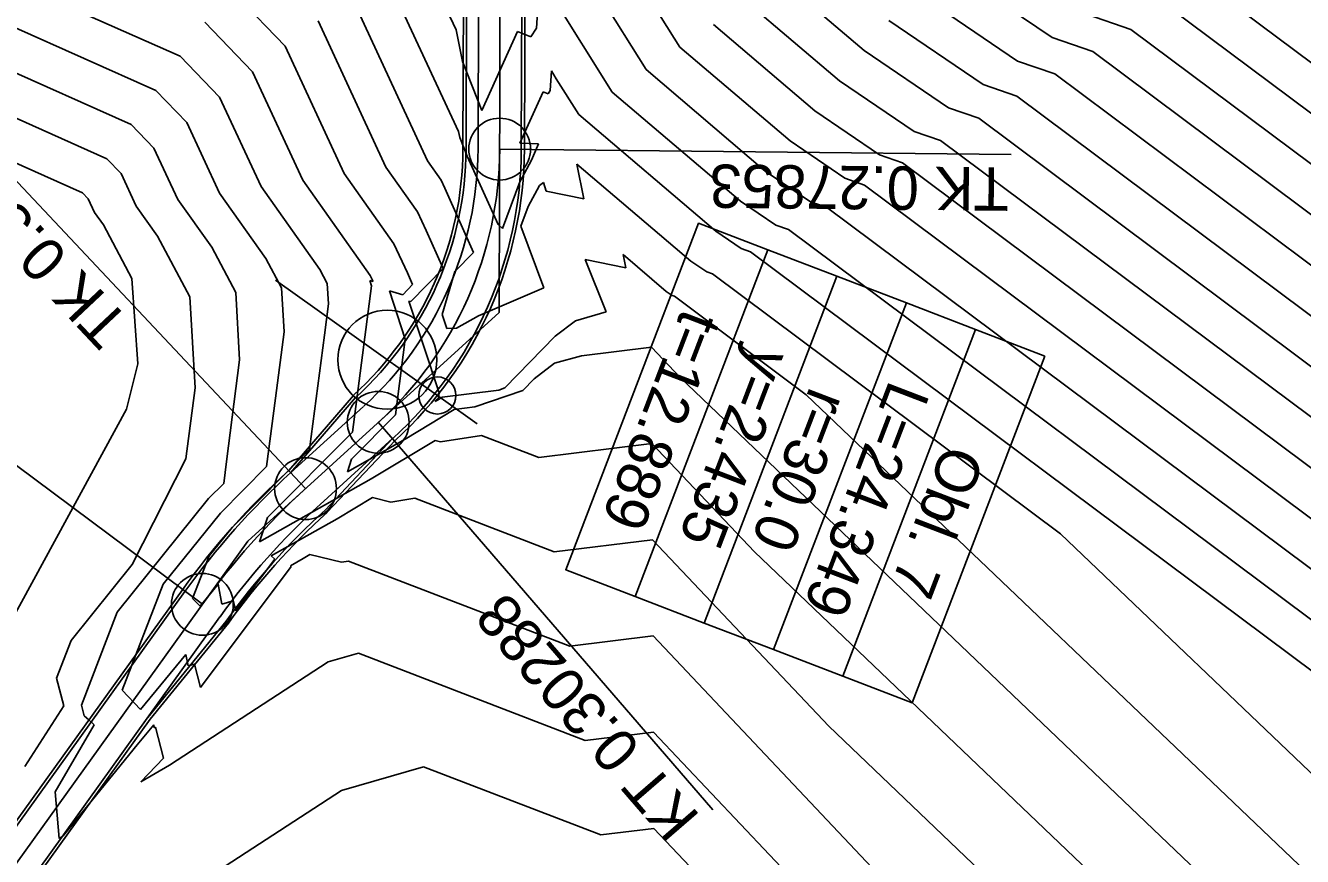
# Model space of a CAD drawing. Extents: x -549394 to -546608, y -1037055 to -1033629.
# Drawn here: x -546964.3 to -546861.1, y -1036015.8 to -1035948.7 of the extents above; entities that cross this region are included whole.
import ezdxf

# ---------------------------------------------------------------- set-up
doc = ezdxf.new("R2010")
doc.units = 0
for name, color, linetype in [('hlavni_vrst', 7, 'Continuous'), ('norm_vrst', 7, 'Continuous'), ('POLYGONY_SITUACE_PO', 7, 'Continuous'), ('u_sirka_7m', 7, 'Continuous'), ('x_navrh_C31', 7, 'Continuous'), ('x_osa_C31', 7, 'Continuous'), ('x_popis_oblouky_C31', 7, 'Continuous'), ('x_popis_pricne_rezy_C31', 7, 'Continuous')]:
    doc.layers.add(name, color=color, linetype=linetype)

msp = doc.modelspace()

# ---------------------------------------------------------------- linework, layer by layer
at = {"layer": 'hlavni_vrst'}
for p, q in [((-546929.53, -1035949), (-546932.73, -1035942.1)), ((-546922.77, -1035944.62), (-546923.02, -1035948.86)), ((-546896.52, -1035950.68), (-546903.28, -1035944.93)), ((-546916.89, -1035954.03), (-546921.74, -1035946.29)), ((-546853.89, -1035960.59), (-546871.88, -1035947.16)), ((-546946, -1035952.39), (-546949.85, -1035948.39)), ((-546929.01, -1035951.57), (-546929.53, -1035949)), ((-546924.57, -1035949.13), (-546927.44, -1035955.51)), ((-546923.47, -1035949.56), (-546924.57, -1035949.13)), ((-546923.02, -1035948.86), (-546923.47, -1035949.56)), ((-546889.7, -1035955.31), (-546896.52, -1035950.68)), ((-546927.44, -1035955.51), (-546929.01, -1035951.57)), ((-546941.93, -1035961.15), (-546946, -1035952.39)), ((-546906.53, -1035962.84), (-546916.89, -1035954.03)), ((-546959.74, -1035962.17), (-546975.08, -1035955.33)), ((-546887.26, -1035956.15), (-546889.7, -1035955.31)), ((-546840.8, -1035990.83), (-546887.26, -1035956.15)), ((-546936.46, -1035968.86), (-546941.93, -1035961.15)), ((-546959.27, -1035962.67), (-546959.74, -1035962.17)), ((-546958.76, -1035963.76), (-546959.27, -1035962.67)), ((-546903.67, -1035964.78), (-546906.53, -1035962.84)), ((-546958.04, -1035964.77), (-546958.76, -1035963.76)), ((-546955.74, -1035969.11), (-546958.04, -1035964.77)), ((-546902.64, -1035965.13), (-546903.67, -1035964.78)), ((-546839.53, -1036012.25), (-546902.64, -1035965.13)), ((-546955.26, -1035976), (-546955.74, -1035969.11)), ((-546937.9, -1035981.51), (-546936.36, -1035969.69)), ((-546936.5, -1035969.27), (-546936.24, -1035969.34)), ((-546936.36, -1035969.69), (-546936.5, -1035969.27)), ((-546936.24, -1035969.34), (-546936.46, -1035968.86)), ((-546956.18, -1035979.65), (-546955.26, -1035976)), ((-546965.68, -1035997.09), (-546956.18, -1035979.65)), ((-546944.77, -1035988.42), (-546937.9, -1035981.51)), ((-546931.23, -1035982.19), (-546936.4, -1035985.3)), ((-546930.79, -1035982.3), (-546931.23, -1035982.19)), ((-546927.47, -1035981.78), (-546930.79, -1035982.3)), ((-546922.83, -1035983.57), (-546927.47, -1035981.78)), ((-546913.69, -1035982.43), (-546922.83, -1035983.57)), ((-546905.4, -1035991.19), (-546913.69, -1035982.43)), ((-546936.4, -1035985.3), (-546945.41, -1035990.38)), ((-546945.41, -1035990.38), (-546944.77, -1035988.42)), ((-546859.63, -1036034.83), (-546905.4, -1035991.19))]:
    msp.add_line(p, q, dxfattribs=at)
at = {"layer": 'norm_vrst'}
for p, q in [((-546911.44, -1035950.39), (-546919.87, -1035936.95)), ((-546914.16, -1035952.21), (-546922.05, -1035939.64)), ((-546881.32, -1035949.63), (-546890.52, -1035943.38)), ((-546929.33, -1035957.21), (-546935.39, -1035944.16)), ((-546943.35, -1035950.33), (-546947.87, -1035945.63)), ((-546884.11, -1035951.53), (-546892.52, -1035945.81)), ((-546856.51, -1035954.54), (-546868.8, -1035945.36)), ((-546951.83, -1035951.14), (-546962.16, -1035946.54)), ((-546931.84, -1035959.58), (-546938.04, -1035946.22)), ((-546898.52, -1035953.11), (-546906, -1035946.75)), ((-546874.96, -1035948.96), (-546878.53, -1035947.74)), ((-546953.81, -1035953.9), (-546965.39, -1035948.74)), ((-546935.2, -1035960.1), (-546940.69, -1035948.27)), ((-546900.52, -1035955.54), (-546908.72, -1035948.57)), ((-546886.91, -1035953.42), (-546894.52, -1035948.24)), ((-546851.27, -1035966.64), (-546874.96, -1035948.96)), ((-546878.03, -1035950.75), (-546881.32, -1035949.63)), ((-546955.79, -1035956.66), (-546968.62, -1035950.94)), ((-546948.65, -1035954.44), (-546951.83, -1035951.14)), ((-546938.57, -1035960.62), (-546943.35, -1035950.33)), ((-546902.52, -1035957.97), (-546911.44, -1035950.39)), ((-546848.65, -1035972.69), (-546878.03, -1035950.75)), ((-546904.52, -1035960.41), (-546914.16, -1035952.21)), ((-546881.11, -1035952.55), (-546884.11, -1035951.53)), ((-546957.77, -1035959.42), (-546971.85, -1035953.14)), ((-546921.81, -1035952.32), (-546921.91, -1035953.91)), ((-546921.43, -1035952.95), (-546921.81, -1035952.32)), ((-546919.61, -1035955.85), (-546921.43, -1035952.95)), ((-546892.49, -1035957.21), (-546898.52, -1035953.11)), ((-546846.04, -1035978.74), (-546881.11, -1035952.55)), ((-546951.31, -1035956.5), (-546953.81, -1035953.9)), ((-546922.49, -1035954.01), (-546924.36, -1035958.17)), ((-546922.08, -1035954.17), (-546922.49, -1035954.01)), ((-546921.91, -1035953.91), (-546922.08, -1035954.17)), ((-546884.19, -1035954.35), (-546886.91, -1035953.42)), ((-546945.3, -1035961.67), (-546948.65, -1035954.44)), ((-546843.42, -1035984.79), (-546884.19, -1035954.35)), ((-546908.53, -1035965.27), (-546919.61, -1035955.85)), ((-546895.29, -1035959.1), (-546900.52, -1035955.54)), ((-546953.96, -1035958.56), (-546955.79, -1035956.66)), ((-546948.66, -1035962.19), (-546951.31, -1035956.5)), ((-546929.23, -1035957.71), (-546929.33, -1035957.21)), ((-546890.34, -1035957.94), (-546892.49, -1035957.21)), ((-546928.63, -1035959.21), (-546929.23, -1035957.71)), ((-546924.36, -1035958.17), (-546922.86, -1035958.22)), ((-546922.86, -1035958.22), (-546923.43, -1035959.54)), ((-546898.08, -1035961), (-546902.52, -1035957.97)), ((-546838.18, -1035996.88), (-546890.34, -1035957.94)), ((-546956.61, -1035960.61), (-546957.77, -1035959.42)), ((-546952.03, -1035962.71), (-546953.96, -1035958.56)), ((-546926.13, -1035964.73), (-546928.63, -1035959.21)), ((-546893.42, -1035959.74), (-546895.29, -1035959.1)), ((-546932.64, -1035963.71), (-546935.2, -1035960.1)), ((-546930.73, -1035961.14), (-546931.84, -1035959.58)), ((-546923.43, -1035959.54), (-546924.36, -1035961.28)), ((-546919.75, -1035959.86), (-546919.2, -1035962.66)), ((-546910.53, -1035967.7), (-546919.75, -1035959.86)), ((-546900.87, -1035962.89), (-546904.52, -1035960.41)), ((-546835.57, -1036002.93), (-546893.42, -1035959.74)), ((-546955.4, -1035963.24), (-546956.61, -1035960.61)), ((-546934.55, -1035966.29), (-546938.57, -1035960.62)), ((-546930.43, -1035961.79), (-546930.73, -1035961.14)), ((-546924.36, -1035961.28), (-546925.78, -1035965.06)), ((-546922.45, -1035961.34), (-546922.78, -1035961.59)), ((-546922.25, -1035962.05), (-546922.45, -1035961.34)), ((-546896.49, -1035961.54), (-546898.08, -1035961)), ((-546832.95, -1036008.98), (-546896.49, -1035961.54)), ((-546944.92, -1035967.47), (-546948.66, -1035962.19)), ((-546940.54, -1035968.38), (-546945.3, -1035961.67)), ((-546928.11, -1035966.99), (-546930.43, -1035961.79)), ((-546922.78, -1035961.59), (-546923.7, -1035963.29)), ((-546919.2, -1035962.66), (-546922.25, -1035962.05)), ((-546953.67, -1035965.67), (-546955.4, -1035963.24)), ((-546949.29, -1035966.57), (-546952.03, -1035962.71)), ((-546923.7, -1035963.29), (-546924.29, -1035964.87)), ((-546899.57, -1035963.33), (-546900.87, -1035962.89)), ((-546830.33, -1036015.03), (-546899.57, -1035963.33)), ((-546931.94, -1035965.22), (-546932.64, -1035963.71)), ((-546951.05, -1035970.59), (-546953.67, -1035965.67)), ((-546930.57, -1035968.29), (-546931.94, -1035965.22)), ((-546925.78, -1035965.06), (-546926.13, -1035964.73)), ((-546924.29, -1035964.87), (-546922.42, -1035969.85)), ((-546906.46, -1035966.68), (-546908.53, -1035965.27)), ((-546947.35, -1035970.22), (-546949.29, -1035966.57)), ((-546933.45, -1035968.65), (-546934.55, -1035966.29)), ((-546905.72, -1035966.93), (-546906.46, -1035966.68)), ((-546943.65, -1035969.86), (-546944.92, -1035967.47)), ((-546929.62, -1035968.54), (-546928.11, -1035966.99)), ((-546915.81, -1035968.23), (-546919.08, -1035967.57)), ((-546919.08, -1035967.57), (-546917.39, -1035971.78)), ((-546916.02, -1035967.16), (-546915.81, -1035968.23)), ((-546912.53, -1035970.14), (-546916.02, -1035967.16)), ((-546909.25, -1035968.57), (-546910.53, -1035967.7)), ((-546860.09, -1036001), (-546905.72, -1035966.93)), ((-546939.95, -1035969.49), (-546940.54, -1035968.38)), ((-546933.04, -1035969.59), (-546933.45, -1035968.65)), ((-546933.19, -1035970.96), (-546930.57, -1035968.29)), ((-546930.65, -1035972.01), (-546929.62, -1035968.54)), ((-546908.8, -1035968.73), (-546909.25, -1035968.57)), ((-546880.65, -1035989.74), (-546908.8, -1035968.73)), ((-546939.85, -1035971.15), (-546939.95, -1035969.49)), ((-546933.84, -1035970.41), (-546933.04, -1035969.59)), ((-546950.63, -1035977.92), (-546951.05, -1035970.59)), ((-546947.04, -1035975.67), (-546947.35, -1035970.22)), ((-546943.44, -1035973.41), (-546943.65, -1035969.86)), ((-546934.92, -1035970.09), (-546933.84, -1035970.41)), ((-546933.63, -1035974.01), (-546934.92, -1035970.09)), ((-546922.42, -1035969.85), (-546927.71, -1035972.12)), ((-546912.05, -1035970.46), (-546912.53, -1035970.14)), ((-546911.87, -1035970.52), (-546912.05, -1035970.46)), ((-546901.21, -1035978.49), (-546911.87, -1035970.52)), ((-546940.17, -1035973.67), (-546939.85, -1035971.15)), ((-546933.35, -1035970.92), (-546933.19, -1035970.96)), ((-546930.9, -1035978.33), (-546933.35, -1035970.92)), ((-546917.39, -1035971.78), (-546919.88, -1035972.51)), ((-546930.26, -1035973.14), (-546930.65, -1035972.01)), ((-546927.71, -1035972.12), (-546929.48, -1035973.1)), ((-546919.88, -1035972.51), (-546921.52, -1035973.77)), ((-546944.13, -1035978.78), (-546943.44, -1035973.41)), ((-546941.37, -1035982.89), (-546940.17, -1035973.67)), ((-546929.48, -1035973.1), (-546930.26, -1035973.14)), ((-546921.52, -1035973.77), (-546925.57, -1035977.94)), ((-546934.43, -1035980.12), (-546933.63, -1035974.01)), ((-546913.73, -1035974.65), (-546919.38, -1035975.36)), ((-546911.41, -1035977.11), (-546913.73, -1035974.65)), ((-546948.09, -1035983.89), (-546947.04, -1035975.67)), ((-546921.57, -1035975.95), (-546923.2, -1035977.2)), ((-546919.38, -1035975.36), (-546921.57, -1035975.95)), ((-546951.37, -1035983.68), (-546950.63, -1035977.92)), ((-546925.57, -1035977.94), (-546926.08, -1035978.11)), ((-546923.2, -1035977.2), (-546924.14, -1035978.16)), ((-546854.08, -1036031.78), (-546911.41, -1035977.11)), ((-546944.85, -1035984.28), (-546944.13, -1035978.78)), ((-546930.9, -1035978.86), (-546931.21, -1035979.03)), ((-546931.21, -1035979.03), (-546931.19, -1035978.96)), ((-546931.19, -1035978.96), (-546930.95, -1035978.73)), ((-546930.95, -1035978.73), (-546930.9, -1035978.33)), ((-546930.64, -1035978.7), (-546930.9, -1035978.86)), ((-546926.08, -1035978.11), (-546930.64, -1035978.7)), ((-546924.14, -1035978.16), (-546928, -1035979.47)), ((-546848.53, -1036028.72), (-546901.21, -1035978.49)), ((-546937.98, -1035983.69), (-546934.43, -1035980.12)), ((-546929.67, -1035979.69), (-546933.65, -1035982.08)), ((-546928, -1035979.47), (-546929.67, -1035979.69)), ((-546933.65, -1035982.08), (-546938.31, -1035984.71)), ((-546947.64, -1035989.21), (-546941.37, -1035982.89)), ((-546955.71, -1035992.22), (-546951.37, -1035983.68)), ((-546948.59, -1035988.05), (-546944.85, -1035984.28)), ((-546948.32, -1035985.67), (-546948.09, -1035983.89)), ((-546938.31, -1035984.71), (-546937.98, -1035983.69)), ((-546949.54, -1035986.89), (-546948.32, -1035985.67)), ((-546956.94, -1035996.07), (-546949.54, -1035986.89)), ((-546936.28, -1035986.8), (-546939.14, -1035988.52)), ((-546934.79, -1035987.17), (-546936.28, -1035986.8)), ((-546932.85, -1035986.86), (-546934.79, -1035987.17)), ((-546921.58, -1035991.19), (-546932.85, -1035986.86)), ((-546953.22, -1035993.79), (-546948.59, -1035988.05)), ((-546949.5, -1035991.51), (-546947.64, -1035989.21)), ((-546939.14, -1035988.52), (-546944.47, -1035991.52)), ((-546913.65, -1035990.21), (-546921.58, -1035991.19)), ((-546899.39, -1036005.27), (-546913.65, -1035990.21)), ((-546842.98, -1036025.66), (-546880.65, -1035989.74)), ((-546950.83, -1035994.96), (-546949.5, -1035991.51)), ((-546941.34, -1035991.4), (-546941.89, -1035991.74)), ((-546938.8, -1035992.03), (-546941.34, -1035991.4)), ((-546960.66, -1035998.36), (-546955.71, -1035992.22)), ((-546942.87, -1035992.37), (-546950.2, -1036002.14)), ((-546944.19, -1035991.77), (-546947.33, -1035995.96)), ((-546944.47, -1035991.52), (-546944.19, -1035991.77)), ((-546941.89, -1035991.74), (-546942.92, -1035992.32)), ((-546942.92, -1035992.32), (-546942.87, -1035992.37)), ((-546938.22, -1035991.94), (-546938.8, -1035992.03)), ((-546920.33, -1035998.82), (-546938.22, -1035991.94)), ((-546956.53, -1036002.38), (-546953.22, -1035993.79)), ((-546948.76, -1035993.79), (-546950.23, -1035995.58)), ((-546948.46, -1035995.42), (-546948.76, -1035993.79)), ((-546950.23, -1035995.58), (-546950.83, -1035994.96)), ((-546947.54, -1035995.16), (-546948.46, -1035995.42)), ((-546947.33, -1035995.96), (-546947.54, -1035995.16)), ((-546959.83, -1036003.57), (-546956.94, -1035996.07)), ((-546961.83, -1036001.39), (-546960.66, -1035998.36)), ((-546913.6, -1035997.98), (-546920.33, -1035998.82)), ((-546893.38, -1036019.35), (-546913.6, -1035997.98)), ((-546951.37, -1035999.49), (-546955.04, -1036003.94)), ((-546951.2, -1036000.41), (-546951.37, -1035999.49)), ((-546937.43, -1035999.39), (-546939.86, -1036000.09)), ((-546919.08, -1036006.45), (-546937.43, -1035999.39)), ((-546939.86, -1036000.09), (-546952.71, -1036008.42)), ((-546950.68, -1036000.26), (-546951.2, -1036000.41)), ((-546950.2, -1036002.14), (-546950.68, -1036000.26)), ((-546961.24, -1036003.64), (-546961.83, -1036001.39)), ((-546955.04, -1036003.94), (-546956.53, -1036002.38)), ((-546964.39, -1036008.54), (-546961.24, -1036003.64)), ((-546961.24, -1036003.64), (-546961.24, -1036003.64)), ((-546961.24, -1036003.64), (-546961.24, -1036003.64)), ((-546959.6, -1036004.45), (-546959.83, -1036003.57)), ((-546959.22, -1036004.76), (-546959.6, -1036004.45)), ((-546958.8, -1036005.16), (-546959.22, -1036004.76)), ((-546961.96, -1036010.58), (-546958.8, -1036005.16)), ((-546953.98, -1036005.18), (-546955.32, -1036006.8)), ((-546953.94, -1036005.4), (-546953.98, -1036005.18)), ((-546953.82, -1036005.37), (-546953.94, -1036005.4)), ((-546953.19, -1036007.87), (-546953.82, -1036005.37)), ((-546913.56, -1036005.76), (-546919.08, -1036006.45)), ((-546887.38, -1036033.42), (-546913.56, -1036005.76)), ((-546865.18, -1036037.89), (-546899.39, -1036005.27)), ((-546955.32, -1036006.8), (-546961.29, -1036014.15)), ((-546955.01, -1036009.77), (-546953.19, -1036007.87)), ((-546952.71, -1036008.42), (-546955.01, -1036009.77)), ((-546932.16, -1036008.56), (-546938.78, -1036010.48)), ((-546917.83, -1036014.07), (-546932.16, -1036008.56)), ((-546961.63, -1036014.36), (-546961.96, -1036010.58)), ((-546938.78, -1036010.48), (-546948.21, -1036016.59)), ((-546961.29, -1036014.15), (-546961.63, -1036014.36)), ((-546913.52, -1036013.54), (-546917.83, -1036014.07)), ((-546881.96, -1036046.88), (-546913.52, -1036013.54))]:
    msp.add_line(p, q, dxfattribs=at)
at = {"layer": 'POLYGONY_SITUACE_PO'}
for centre in [(-546926, -1035958.64), (-546935.82, -1035980.72), (-546941.7, -1035986.08), (-546950.04, -1035995.43)]:
    msp.add_circle(centre, 2.5, dxfattribs=at)
at = {"layer": 'u_sirka_7m'}
for centre, radius in [((-546935.09, -1035975.66), 4), ((-546931.04, -1035978.55), 1.5)]:
    msp.add_circle(centre, radius, dxfattribs=at)
at = {"layer": 'x_navrh_C31'}
for p, q in [((-546928.97, -1035958.63), (-546928.92, -1035943.59)), ((-546928.72, -1035958.63), (-546928.67, -1035943.6)), ((-546927.75, -1035958.63), (-546927.7, -1035943.6)), ((-546924.25, -1035958.64), (-546924.2, -1035943.61)), ((-546937.83, -1035978.54), (-546943.06, -1035984.61)), ((-546937.65, -1035978.71), (-546942.88, -1035984.78)), ((-546942.88, -1035984.78), (-546937, -1035979.43)), ((-546940.53, -1035987.37), (-546934.63, -1035982.01)), ((-546940.12, -1035987.82), (-546934.63, -1035982.01)), ((-546939.94, -1035987.99), (-546934.45, -1035982.18)), ((-547002.86, -1036065.86), (-546951.46, -1035994.4)), ((-547000.02, -1036067.9), (-546948.62, -1035996.45)), ((-546948.13, -1035996.8), (-546954.46, -1036004.57)), ((-546947.93, -1035996.95), (-546954.26, -1036004.72))]:
    msp.add_line(p, q, dxfattribs=at)
for points in [[(-546924, -1035958.64), (-546923.95, -1035943.61)], [(-546997.24, -1036057.61), (-546951.66, -1035994.26)], [(-546999.81, -1036068.05), (-546954.26, -1036004.72)]]:
    msp.add_lwpolyline(points, dxfattribs=at)
for centre, radius, start, end in [((-546956, -1035958.53), 27.03, 312.2581, 359.7992), ((-546956, -1035958.53), 27.28, 312.2902, 359.7992), ((-546956, -1035958.53), 28.25, 312.2902, 359.7992), ((-546956, -1035958.53), 31.75, 312.2902, 359.7992), ((-546956, -1035958.53), 32, 312.3431, 359.7992), ((-546901.33, -1036030.46), 62, 132.3042, 144.2713), ((-546901.33, -1036030.46), 61.75, 132.2902, 144.2713), ((-546901.33, -1036030.46), 58.25, 132.2902, 144.2713), ((-546901.33, -1036030.46), 57.65, 132.2902, 144.2713), ((-546901.33, -1036030.46), 57.4, 132.2902, 144.2788)]:
    msp.add_arc(centre, radius, start, end, dxfattribs=at)
at = {"layer": 'x_osa_C31'}
msp.add_lwpolyline([(-547007, -1036074.62), (-546946.36, -1035990.32), (-546926.05, -1035971.84), (-546925.92, -1035933.3), (-546935.95, -1035920.32)], dxfattribs=at)
for centre, radius, start, end in [((-546956, -1035958.53), 30, 312.2902, 359.7992), ((-546901.33, -1036030.46), 60, 132.2902, 144.2713)]:
    msp.add_arc(centre, radius, start, end, dxfattribs=at)
at = {"layer": 'x_popis_oblouky_C31'}
for points in [[(-546941.7, -1035986.08), (-546970.07, -1035955.96)], [(-546884.63, -1035959.07), (-546926, -1035958.64)], [(-546950.04, -1035995.43), (-546983.22, -1035970.71)], [(-546908.77, -1036012.03), (-546935.82, -1035980.72)]]:
    msp.add_lwpolyline(points, dxfattribs=at)
for points in [[(-546904.32, -1035966.78), (-546915.05, -1035994.79), (-546920.66, -1035992.64), (-546909.92, -1035964.63)], [(-546898.72, -1035968.92), (-546909.45, -1035996.94), (-546915.05, -1035994.79), (-546904.32, -1035966.78)], [(-546893.11, -1035971.07), (-546903.85, -1035999.08), (-546909.45, -1035996.94), (-546898.72, -1035968.92)], [(-546887.51, -1035973.22), (-546898.25, -1036001.23), (-546903.85, -1035999.08), (-546893.11, -1035971.07)], [(-546881.91, -1035975.37), (-546892.64, -1036003.38), (-546898.25, -1036001.23), (-546887.51, -1035973.22)]]:
    msp.add_lwpolyline(points, close=True, dxfattribs=at)
at = {"layer": 'x_popis_pricne_rezy_C31'}
msp.add_lwpolyline([(-546927.83, -1035980.84), (-546935.98, -1035975.03), (-546944.12, -1035969.22)], dxfattribs=at)

# ---------------------------------------------------------------- texts
at = {"layer": 'x_popis_oblouky_C31'}
for s, rotation, p in [('TK 0.31217', 133.2795, (-546955.77, -1035972.6)), ('TK 0.27853', 179.395, (-546884.8, -1035960.13)), ('t=12.889', 249.0513, (-546911.22, -1035971.4)), ('y=2.435', 249.0513, (-546905.54, -1035974.33)), ('r=30.0', 249.0513, (-546900.89, -1035977.73)), ('L=24.349', 249.0513, (-546894.45, -1035977.2)), ('Obl. 7', 249.0513, (-546890, -1035982.35)), ('KT 0.30288', 130.8242, (-546909.7, -1036012.58))]:
    msp.add_text(s, height=3.5, rotation=rotation, dxfattribs=at).set_placement(p)

doc.saveas('drawing.dxf')
